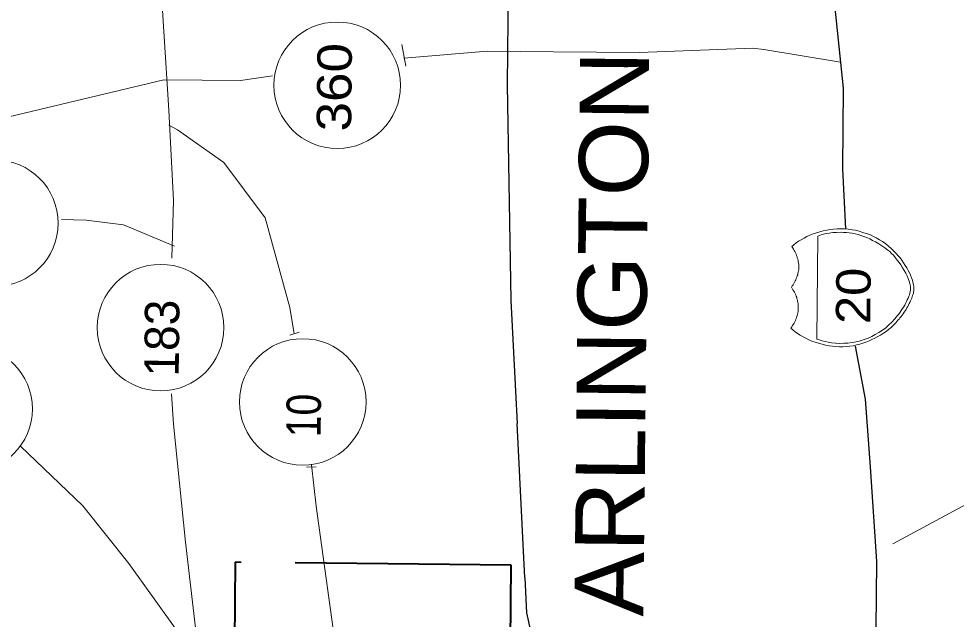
# Model space of a CAD drawing. Extents: x 2356576 to 2377878, y 6966390 to 6990634.
# Drawn here: x 2365828.3 to 2366013.1, y 6969001.5 to 6969120 of the extents above; entities that cross this region are included whole.
import ezdxf

# ---------------------------------------------------------------- set-up
doc = ezdxf.new("R2010")
doc.units = 0
doc.header["$LTSCALE"] = 7.1
doc.linetypes.add('LONG_DASHED', pattern=[7.5, 6, -1.5])
doc.layers.add('19', color=7, linetype='Continuous', lineweight=13)
doc.layers.add('8', color=7, linetype='Continuous', lineweight=13)

msp = doc.modelspace()

# ---------------------------------------------------------------- linework, layer by layer
at = {"layer": '19'}
for p, q in [((2365904.616, 6969110.688), (2365903.821, 6969114.957)), ((2365972.997, 6969114.24), (2365975.214, 6969113.945)), ((2365920.728, 6969113.642), (2365904.18, 6969112.221)), ((2365975.214, 6969113.945), (2365990.313, 6969111.421)), ((2365872.033, 6969107.814), (2365878.283, 6969108.741)), ((2365856.914, 6969107.97), (2365872.033, 6969107.814)), ((2365859.571, 6969098.07), (2365857.841, 6969098.988)), ((2365858.767, 6969084.158), (2365858.437, 6969072.793)), ((2365841.562, 6969080.288), (2365836.703, 6969080.426)), ((2365881.709, 6969063.011), (2365882.528, 6969058.258)), ((2365881.741, 6969057.547), (2365883.547, 6969058.128)), ((2365882.583, 6969057.81), (2365882.528, 6969058.258)), ((2365858.758, 6969040.024), (2365858.372, 6969046)), ((2365840.889, 6969023.86), (2365828.591, 6969035.656)), ((2365884.983, 6969031.504), (2365886.932, 6969031.603)), ((2365886.944, 6969023.831), (2365886.008, 6969032.001))]:
    msp.add_line(p, q, dxfattribs=at)
at = {"layer": '19', "lineweight": 25}
msp.add_line((2365928.079, 6969009.664), (2365926.535, 6969040.134), dxfattribs=at)
at = {"layer": '19'}
for points in [[(2365858.767, 6969084.158), (2365857.839, 6969101.96), (2365855.882, 6969133.094), (2365857.437, 6969161.612), (2365858.594, 6969180.589), (2365859.115, 6969204.617), (2365855.958, 6969218.422), (2365846.578, 6969234.36), (2365837.794, 6969252.124), (2365836.317, 6969257.48)], [(2366155.514, 6969175.953), (2366151.383, 6969165.227), (2366148.79, 6969152.413), (2366143.811, 6969129.392), (2366135.33, 6969115.799), (2366129.355, 6969106.648), (2366121.344, 6969094.85), (2366108.711, 6969083.249), (2366095.035, 6969075.202), (2366079.714, 6969067.44), (2366061.538, 6969056.344), (2366050.004, 6969046.563), (2366038.586, 6969039.093), (2366024.252, 6969030.869), (2366017.685, 6969025.629), (2366000.609, 6969016.381)], [(2365920.728, 6969113.642), (2365933.687, 6969113.507), (2365950.698, 6969113.331), (2365972.997, 6969114.24)], [(2365856.914, 6969107.97), (2365819.074, 6969098.97), (2365792.738, 6969085.174)], [(2365881.709, 6969063.011), (2365876.852, 6969080.702), (2365868.713, 6969091.615), (2365859.571, 6969098.07)], [(2365859.002, 6969075.155), (2365848.936, 6969079.312), (2365841.562, 6969080.288)], [(2365981.222, 6969068.009), (2365981.373, 6969068.279), (2365981.496, 6969068.518), (2365981.59, 6969068.757), (2365981.713, 6969069.024), (2365981.744, 6969069.295), (2365981.866, 6969069.502), (2365981.901, 6969069.774), (2365981.963, 6969070.013), (2365982.026, 6969070.28), (2365982.056, 6969070.52), (2365982.059, 6969070.792), (2365982.062, 6969071.06), (2365982.064, 6969071.3), (2365982.067, 6969071.54), (2365982.042, 6969071.812), (2365981.984, 6969072.053), (2365981.927, 6969072.293), (2365981.898, 6969072.562), (2365981.78, 6969072.803), (2365981.755, 6969073.043), (2365981.637, 6969073.317), (2365981.548, 6969073.585), (2365981.431, 6969073.827), (2365981.285, 6969074.068), (2365981.168, 6969074.309), (2365981.018, 6969074.551), (2365980.841, 6969074.853), (2365980.696, 6969075.094), (2365981.087, 6969075.422), (2365981.543, 6969075.778), (2365982.026, 6969076.101), (2365982.569, 6969076.395), (2365983.112, 6969076.689), (2365983.684, 6969077.016), (2365984.259, 6969077.278), (2365984.889, 6969077.543), (2365985.551, 6969077.744), (2365986.214, 6969077.949), (2365986.908, 6969078.15), (2365987.597, 6969078.295), (2365988.29, 6969078.408), (2365988.951, 6969078.489), (2365989.64, 6969078.542), (2365990.332, 6969078.567), (2365991.08, 6969078.527), (2365991.831, 6969078.459), (2365992.578, 6969078.363), (2365993.269, 6969078.264), (2365993.988, 6969078.109), (2365994.705, 6969077.861), (2365995.391, 6969077.642), (2365996.081, 6969077.427), (2365996.706, 6969077.121), (2365997.362, 6969076.754), (2365997.99, 6969076.415), (2365998.586, 6969076.021), (2365999.21, 6969075.595), (2365999.777, 6969075.137), (2366000.312, 6969074.651), (2366000.875, 6969074.105), (2366001.262, 6969073.681), (2366001.646, 6969073.257), (2366002.033, 6969072.805), (2366002.388, 6969072.35), (2366002.711, 6969071.838), (2366003.066, 6969071.322), (2366003.361, 6969070.839), (2366003.628, 6969070.357), (2366003.891, 6969069.874), (2366004.126, 6969069.391), (2366004.333, 6969068.909), (2366004.476, 6969068.4), (2366004.592, 6969068.006), (2366004.679, 6969067.558), (2366004.763, 6969067.165), (2366004.759, 6969066.805)], [(2366004.759, 6969066.805), (2366004.757, 6969066.565), (2366004.754, 6969066.357), (2366004.692, 6969066.085), (2366004.662, 6969065.878), (2366004.599, 6969065.666), (2366004.505, 6969065.399), (2366004.442, 6969065.128), (2366004.351, 6969064.861), (2366004.228, 6969064.59), (2366004.105, 6969064.323), (2366003.982, 6969064.025), (2366003.86, 6969063.786), (2366003.705, 6969063.487), (2366003.554, 6969063.217), (2366003.399, 6969062.951), (2366003.248, 6969062.652), (2366003.033, 6969062.382), (2366002.85, 6969062.084), (2366002.667, 6969061.786), (2366002.457, 6969061.548), (2366002.274, 6969061.282), (2366002.031, 6969061.013), (2366001.848, 6969060.714), (2366001.634, 6969060.505), (2366001.423, 6969060.239), (2366001.208, 6969060.001), (2366000.966, 6969059.732), (2366000.724, 6969059.526), (2366000.481, 6969059.289), (2366000.271, 6969059.079), (2366000.057, 6969058.901), (2365999.787, 6969058.696), (2365999.303, 6969058.309), (2365998.759, 6969057.954), (2365998.183, 6969057.6), (2365997.672, 6969057.306), (2365997.097, 6969056.983), (2365996.494, 6969056.69), (2365995.923, 6969056.424), (2365995.321, 6969056.19), (2365994.719, 6969055.988), (2365994.084, 6969055.783), (2365993.455, 6969055.641), (2365992.821, 6969055.496), (2365992.16, 6969055.383), (2365991.5, 6969055.329), (2365990.779, 6969055.277), (2365990.091, 6969055.256), (2365989.399, 6969055.323), (2365988.712, 6969055.39), (2365988.053, 6969055.457), (2365987.362, 6969055.612), (2365986.676, 6969055.771), (2365985.986, 6969055.959), (2365985.328, 6969056.173), (2365984.67, 6969056.392), (2365984.045, 6969056.667), (2365983.476, 6969056.945), (2365982.911, 6969057.25), (2365982.374, 6969057.584), (2365981.838, 6969057.922), (2365981.361, 6969058.227), (2365980.913, 6969058.591), (2365980.528, 6969058.923), (2365980.679, 6969059.194), (2365980.862, 6969059.46), (2365981.017, 6969059.73), (2365981.139, 6969059.937), (2365981.29, 6969060.207), (2365981.412, 6969060.446), (2365981.507, 6969060.713), (2365981.63, 6969060.984), (2365981.66, 6969061.224), (2365981.783, 6969061.462), (2365981.817, 6969061.734), (2365981.88, 6969061.973), (2365981.943, 6969062.241), (2365981.973, 6969062.48), (2365981.976, 6969062.72), (2365981.979, 6969063.02), (2365981.981, 6969063.232), (2365981.984, 6969063.5), (2365981.958, 6969063.741), (2365981.901, 6969064.013), (2365981.843, 6969064.254), (2365981.814, 6969064.494), (2365981.697, 6969064.763), (2365981.672, 6969065.036), (2365981.554, 6969065.245), (2365981.465, 6969065.518), (2365981.347, 6969065.787), (2365981.202, 6969066.061), (2365981.084, 6969066.27), (2365980.935, 6969066.543), (2365980.758, 6969066.785), (2365980.612, 6969067.055), (2365980.763, 6969067.293), (2365980.945, 6969067.503), (2365981.1, 6969067.77), (2365981.222, 6969068.009)], [(2365864.052, 6968991.934), (2365861.157, 6969016.718), (2365858.758, 6969040.024)], [(2365840.889, 6969023.86), (2365850.012, 6969012.481), (2365864.416, 6968992.29)], [(2365886.944, 6969023.831), (2365890.88, 6968995.288), (2365892.792, 6968930.793), (2365894.338, 6968920.933)]]:
    msp.add_lwpolyline(points, dxfattribs=at)
at = {"layer": '19', "lineweight": 25}
for points in [[(2365915.489, 6969256.66), (2365917.015, 6969239.123), (2365920.491, 6969212.413), (2365923.907, 6969180.304), (2365924.96, 6969145.7), (2365924.559, 6969106.97), (2365925.286, 6969064.388), (2365926.535, 6969040.134)], [(2366011.996, 6969255.66), (2366002.067, 6969238.242), (2365996.913, 6969215.73), (2365990.557, 6969192.935), (2365988.816, 6969161.211), (2365987.454, 6969142.5), (2365988.484, 6969129.141), (2365990.827, 6969106.283), (2365990.663, 6969090.412), (2365991.32, 6969078.497)], [(2365993.212, 6969055.404), (2365995.144, 6969044.943), (2365996.174, 6969031.612), (2365997.392, 6969012.874), (2365997.254, 6968999.555), (2365998.323, 6968990.003), (2366002.006, 6968983.305), (2366004.476, 6968969.926), (2366002.874, 6968951.222), (2366001.496, 6968934.107), (2366000.162, 6968915.368), (2366003.604, 6968885.811), (2365999.567, 6968857.919), (2365994.142, 6968835.442), (2365986.716, 6968822.166), (2365969.062, 6968818.241), (2365951.423, 6968818.424), (2365942.698, 6968815.994), (2365930.315, 6968822.751)], [(2365928.079, 6969009.664), (2365928.4, 6969002.788), (2365929.974, 6968995.604)]]:
    msp.add_lwpolyline(points, dxfattribs=at)
at = {"layer": '19'}
msp.add_lwpolyline([(2365985.845, 6969077.113), (2365985.634, 6969056.802), (2365985.934, 6969056.707), (2365986.292, 6969056.555), (2365986.711, 6969056.431), (2365987.282, 6969056.333), (2365987.848, 6969056.179), (2365988.539, 6969056.052), (2365989.286, 6969055.984), (2365990.098, 6969055.944), (2365990.938, 6969055.967), (2365991.779, 6969056.019), (2365992.62, 6969056.13), (2365993.401, 6969056.27), (2365994.212, 6969056.473), (2365994.966, 6969056.706), (2365995.749, 6969056.997), (2365996.472, 6969057.318), (2365997.164, 6969057.671), (2365997.888, 6969058.083), (2365998.553, 6969058.528), (2365999.218, 6969059.03), (2365999.856, 6969059.595), (2366000.43, 6969060.157), (2366001.009, 6969060.783), (2366001.523, 6969061.438), (2366001.826, 6969061.735), (2366002.042, 6969062.093), (2366002.286, 6969062.422), (2366002.498, 6969062.808), (2366002.713, 6969063.106), (2366002.956, 6969063.463), (2366003.14, 6969063.821), (2366003.324, 6969064.211), (2366003.476, 6969064.538), (2366003.631, 6969064.896), (2366003.783, 6969065.255), (2366003.878, 6969065.554), (2366003.97, 6969065.885), (2366004.033, 6969066.184), (2366004.096, 6969066.512), (2366004.099, 6969066.811), (2366004.076, 6969067.232), (2366003.989, 6969067.745), (2366003.813, 6969068.195), (2366003.639, 6969068.768), (2366003.465, 6969069.278), (2366003.17, 6969069.793), (2366002.876, 6969070.336), (2366002.553, 6969070.88), (2366002.199, 6969071.423), (2366001.844, 6969071.907), (2366001.489, 6969072.391), (2366001.102, 6969072.875), (2366000.746, 6969073.327), (2366000.362, 6969073.691), (2366000.006, 6969074.054), (2365999.649, 6969074.33), (2365999.053, 6969074.784), (2365998.426, 6969075.211), (2365997.862, 6969075.609), (2365997.206, 6969075.975), (2365996.637, 6969076.281), (2365996.072, 6969076.555), (2365995.503, 6969076.833), (2365994.905, 6969077.047), (2365994.307, 6969077.265), (2365993.769, 6969077.451), (2365993.17, 6969077.577), (2365992.603, 6969077.671), (2365992.032, 6969077.737), (2365991.465, 6969077.835), (2365990.893, 6969077.841), (2365990.325, 6969077.875), (2365989.513, 6969077.855), (2365988.764, 6969077.803), (2365988.071, 6969077.718), (2365987.502, 6969077.636), (2365986.929, 6969077.49), (2365986.507, 6969077.346), (2365986.146, 6969077.23)], close=True, dxfattribs=at)
at = {"layer": '19', "linetype": 'LONG_DASHED', "lineweight": 40}
msp.add_lwpolyline([(2365875.35, 6968982.009), (2365925.059, 6968981.494), (2365925.377, 6969012.18), (2365870.956, 6969012.744), (2365870.638, 6968982.057)], close=True, dxfattribs=at)
at = {"layer": '19'}
for centre in [(2365891.07, 6969106.881), (2365823.565, 6969079.667), (2365856.243, 6969059.06), (2365884.28, 6969044.389), (2365818.484, 6969043.016)]:
    msp.add_circle(centre, 12.486, dxfattribs=at)
at = {"layer": '8'}
for p, q in [((2365904.616, 6969110.688), (2365903.821, 6969114.957)), ((2365972.997, 6969114.24), (2365975.214, 6969113.945)), ((2365920.728, 6969113.642), (2365904.18, 6969112.221)), ((2365975.214, 6969113.945), (2365990.313, 6969111.421)), ((2365872.033, 6969107.814), (2365878.283, 6969108.741)), ((2365856.914, 6969107.97), (2365872.033, 6969107.814)), ((2365859.571, 6969098.07), (2365857.841, 6969098.988)), ((2365858.767, 6969084.158), (2365858.437, 6969072.793)), ((2365841.562, 6969080.288), (2365836.703, 6969080.426)), ((2365881.709, 6969063.011), (2365882.528, 6969058.258)), ((2365881.741, 6969057.547), (2365883.547, 6969058.128)), ((2365882.583, 6969057.81), (2365882.528, 6969058.258)), ((2365858.758, 6969040.024), (2365858.372, 6969046)), ((2365840.889, 6969023.86), (2365828.591, 6969035.656)), ((2365884.983, 6969031.504), (2365886.932, 6969031.603)), ((2365886.944, 6969023.831), (2365886.008, 6969032.001))]:
    msp.add_line(p, q, dxfattribs=at)
at = {"layer": '8', "lineweight": 25}
msp.add_line((2365928.079, 6969009.664), (2365926.535, 6969040.134), dxfattribs=at)
at = {"layer": '8'}
for points in [[(2365858.767, 6969084.158), (2365857.839, 6969101.96), (2365855.882, 6969133.094), (2365857.437, 6969161.612), (2365858.594, 6969180.589), (2365859.115, 6969204.617), (2365855.958, 6969218.422), (2365846.578, 6969234.36), (2365837.794, 6969252.124), (2365836.317, 6969257.48)], [(2366155.514, 6969175.953), (2366151.383, 6969165.227), (2366148.79, 6969152.413), (2366143.811, 6969129.392), (2366135.33, 6969115.799), (2366129.355, 6969106.648), (2366121.344, 6969094.85), (2366108.711, 6969083.249), (2366095.035, 6969075.202), (2366079.714, 6969067.44), (2366061.538, 6969056.344), (2366050.004, 6969046.563), (2366038.586, 6969039.093), (2366024.252, 6969030.869), (2366017.685, 6969025.629), (2366000.609, 6969016.381)], [(2365920.728, 6969113.642), (2365933.687, 6969113.507), (2365950.698, 6969113.331), (2365972.997, 6969114.24)], [(2365856.914, 6969107.97), (2365819.074, 6969098.97), (2365792.738, 6969085.174)], [(2365881.709, 6969063.011), (2365876.852, 6969080.702), (2365868.713, 6969091.615), (2365859.571, 6969098.07)], [(2365859.002, 6969075.155), (2365848.936, 6969079.312), (2365841.562, 6969080.288)], [(2365981.222, 6969068.009), (2365981.373, 6969068.279), (2365981.496, 6969068.518), (2365981.59, 6969068.757), (2365981.713, 6969069.024), (2365981.744, 6969069.295), (2365981.866, 6969069.502), (2365981.901, 6969069.774), (2365981.963, 6969070.013), (2365982.026, 6969070.28), (2365982.056, 6969070.52), (2365982.059, 6969070.792), (2365982.062, 6969071.06), (2365982.064, 6969071.3), (2365982.067, 6969071.54), (2365982.042, 6969071.812), (2365981.984, 6969072.053), (2365981.927, 6969072.293), (2365981.898, 6969072.562), (2365981.78, 6969072.803), (2365981.755, 6969073.043), (2365981.637, 6969073.317), (2365981.548, 6969073.585), (2365981.431, 6969073.827), (2365981.285, 6969074.068), (2365981.168, 6969074.309), (2365981.018, 6969074.551), (2365980.841, 6969074.853), (2365980.696, 6969075.094), (2365981.087, 6969075.422), (2365981.543, 6969075.778), (2365982.026, 6969076.101), (2365982.569, 6969076.395), (2365983.112, 6969076.689), (2365983.684, 6969077.016), (2365984.259, 6969077.278), (2365984.889, 6969077.543), (2365985.551, 6969077.744), (2365986.214, 6969077.949), (2365986.908, 6969078.15), (2365987.597, 6969078.295), (2365988.29, 6969078.408), (2365988.951, 6969078.489), (2365989.64, 6969078.542), (2365990.332, 6969078.567), (2365991.08, 6969078.527), (2365991.831, 6969078.459), (2365992.578, 6969078.363), (2365993.269, 6969078.264), (2365993.988, 6969078.109), (2365994.705, 6969077.861), (2365995.391, 6969077.642), (2365996.081, 6969077.427), (2365996.706, 6969077.121), (2365997.362, 6969076.754), (2365997.99, 6969076.415), (2365998.586, 6969076.021), (2365999.21, 6969075.595), (2365999.777, 6969075.137), (2366000.312, 6969074.651), (2366000.875, 6969074.105), (2366001.262, 6969073.681), (2366001.646, 6969073.257), (2366002.033, 6969072.805), (2366002.388, 6969072.35), (2366002.711, 6969071.838), (2366003.066, 6969071.322), (2366003.361, 6969070.839), (2366003.628, 6969070.357), (2366003.891, 6969069.874), (2366004.126, 6969069.391), (2366004.333, 6969068.909), (2366004.476, 6969068.4), (2366004.592, 6969068.006), (2366004.679, 6969067.558), (2366004.763, 6969067.165), (2366004.759, 6969066.805)], [(2366004.759, 6969066.805), (2366004.757, 6969066.565), (2366004.754, 6969066.357), (2366004.692, 6969066.085), (2366004.662, 6969065.878), (2366004.599, 6969065.666), (2366004.505, 6969065.399), (2366004.442, 6969065.128), (2366004.351, 6969064.861), (2366004.228, 6969064.59), (2366004.105, 6969064.323), (2366003.982, 6969064.025), (2366003.86, 6969063.786), (2366003.705, 6969063.487), (2366003.554, 6969063.217), (2366003.399, 6969062.951), (2366003.248, 6969062.652), (2366003.033, 6969062.382), (2366002.85, 6969062.084), (2366002.667, 6969061.786), (2366002.457, 6969061.548), (2366002.274, 6969061.282), (2366002.031, 6969061.013), (2366001.848, 6969060.714), (2366001.634, 6969060.505), (2366001.423, 6969060.239), (2366001.208, 6969060.001), (2366000.966, 6969059.732), (2366000.724, 6969059.526), (2366000.481, 6969059.289), (2366000.271, 6969059.079), (2366000.057, 6969058.901), (2365999.787, 6969058.696), (2365999.303, 6969058.309), (2365998.759, 6969057.954), (2365998.183, 6969057.6), (2365997.672, 6969057.306), (2365997.097, 6969056.983), (2365996.494, 6969056.69), (2365995.923, 6969056.424), (2365995.321, 6969056.19), (2365994.719, 6969055.988), (2365994.084, 6969055.783), (2365993.455, 6969055.641), (2365992.821, 6969055.496), (2365992.16, 6969055.383), (2365991.5, 6969055.329), (2365990.779, 6969055.277), (2365990.091, 6969055.256), (2365989.399, 6969055.323), (2365988.712, 6969055.39), (2365988.053, 6969055.457), (2365987.362, 6969055.612), (2365986.676, 6969055.771), (2365985.986, 6969055.959), (2365985.328, 6969056.173), (2365984.67, 6969056.392), (2365984.045, 6969056.667), (2365983.476, 6969056.945), (2365982.911, 6969057.25), (2365982.374, 6969057.584), (2365981.838, 6969057.922), (2365981.361, 6969058.227), (2365980.913, 6969058.591), (2365980.528, 6969058.923), (2365980.679, 6969059.194), (2365980.862, 6969059.46), (2365981.017, 6969059.73), (2365981.139, 6969059.937), (2365981.29, 6969060.207), (2365981.412, 6969060.446), (2365981.507, 6969060.713), (2365981.63, 6969060.984), (2365981.66, 6969061.224), (2365981.783, 6969061.462), (2365981.817, 6969061.734), (2365981.88, 6969061.973), (2365981.943, 6969062.241), (2365981.973, 6969062.48), (2365981.976, 6969062.72), (2365981.979, 6969063.02), (2365981.981, 6969063.232), (2365981.984, 6969063.5), (2365981.958, 6969063.741), (2365981.901, 6969064.013), (2365981.843, 6969064.254), (2365981.814, 6969064.494), (2365981.697, 6969064.763), (2365981.672, 6969065.036), (2365981.554, 6969065.245), (2365981.465, 6969065.518), (2365981.347, 6969065.787), (2365981.202, 6969066.061), (2365981.084, 6969066.27), (2365980.935, 6969066.543), (2365980.758, 6969066.785), (2365980.612, 6969067.055), (2365980.763, 6969067.293), (2365980.945, 6969067.503), (2365981.1, 6969067.77), (2365981.222, 6969068.009)], [(2365864.052, 6968991.934), (2365861.157, 6969016.718), (2365858.758, 6969040.024)], [(2365840.889, 6969023.86), (2365850.012, 6969012.481), (2365864.416, 6968992.29)], [(2365886.944, 6969023.831), (2365890.88, 6968995.288), (2365892.792, 6968930.793), (2365894.338, 6968920.933)]]:
    msp.add_lwpolyline(points, dxfattribs=at)
at = {"layer": '8', "lineweight": 25}
for points in [[(2365915.489, 6969256.66), (2365917.015, 6969239.123), (2365920.491, 6969212.413), (2365923.907, 6969180.304), (2365924.96, 6969145.7), (2365924.559, 6969106.97), (2365925.286, 6969064.388), (2365926.535, 6969040.134)], [(2366011.996, 6969255.66), (2366002.067, 6969238.242), (2365996.913, 6969215.73), (2365990.557, 6969192.935), (2365988.816, 6969161.211), (2365987.454, 6969142.5), (2365988.484, 6969129.141), (2365990.827, 6969106.283), (2365990.663, 6969090.412), (2365991.32, 6969078.497)], [(2365993.212, 6969055.404), (2365995.144, 6969044.943), (2365996.174, 6969031.612), (2365997.392, 6969012.874), (2365997.254, 6968999.555), (2365998.323, 6968990.003), (2366002.006, 6968983.305), (2366004.476, 6968969.926), (2366002.874, 6968951.222), (2366001.496, 6968934.107), (2366000.162, 6968915.368), (2366003.604, 6968885.811), (2365999.567, 6968857.919), (2365994.142, 6968835.442), (2365986.716, 6968822.166), (2365969.062, 6968818.241), (2365951.423, 6968818.424), (2365942.698, 6968815.994), (2365930.315, 6968822.751)], [(2365928.079, 6969009.664), (2365928.4, 6969002.788), (2365929.974, 6968995.604)]]:
    msp.add_lwpolyline(points, dxfattribs=at)
at = {"layer": '8'}
msp.add_lwpolyline([(2365985.845, 6969077.113), (2365985.634, 6969056.802), (2365985.934, 6969056.707), (2365986.292, 6969056.555), (2365986.711, 6969056.431), (2365987.282, 6969056.333), (2365987.848, 6969056.179), (2365988.539, 6969056.052), (2365989.286, 6969055.984), (2365990.098, 6969055.944), (2365990.938, 6969055.967), (2365991.779, 6969056.019), (2365992.62, 6969056.13), (2365993.401, 6969056.27), (2365994.212, 6969056.473), (2365994.966, 6969056.706), (2365995.749, 6969056.997), (2365996.472, 6969057.318), (2365997.164, 6969057.671), (2365997.888, 6969058.083), (2365998.553, 6969058.528), (2365999.218, 6969059.03), (2365999.856, 6969059.595), (2366000.43, 6969060.157), (2366001.009, 6969060.783), (2366001.523, 6969061.438), (2366001.826, 6969061.735), (2366002.042, 6969062.093), (2366002.286, 6969062.422), (2366002.498, 6969062.808), (2366002.713, 6969063.106), (2366002.956, 6969063.463), (2366003.14, 6969063.821), (2366003.324, 6969064.211), (2366003.476, 6969064.538), (2366003.631, 6969064.896), (2366003.783, 6969065.255), (2366003.878, 6969065.554), (2366003.97, 6969065.885), (2366004.033, 6969066.184), (2366004.096, 6969066.512), (2366004.099, 6969066.811), (2366004.076, 6969067.232), (2366003.989, 6969067.745), (2366003.813, 6969068.195), (2366003.639, 6969068.768), (2366003.465, 6969069.278), (2366003.17, 6969069.793), (2366002.876, 6969070.336), (2366002.553, 6969070.88), (2366002.199, 6969071.423), (2366001.844, 6969071.907), (2366001.489, 6969072.391), (2366001.102, 6969072.875), (2366000.746, 6969073.327), (2366000.362, 6969073.691), (2366000.006, 6969074.054), (2365999.649, 6969074.33), (2365999.053, 6969074.784), (2365998.426, 6969075.211), (2365997.862, 6969075.609), (2365997.206, 6969075.975), (2365996.637, 6969076.281), (2365996.072, 6969076.555), (2365995.503, 6969076.833), (2365994.905, 6969077.047), (2365994.307, 6969077.265), (2365993.769, 6969077.451), (2365993.17, 6969077.577), (2365992.603, 6969077.671), (2365992.032, 6969077.737), (2365991.465, 6969077.835), (2365990.893, 6969077.841), (2365990.325, 6969077.875), (2365989.513, 6969077.855), (2365988.764, 6969077.803), (2365988.071, 6969077.718), (2365987.502, 6969077.636), (2365986.929, 6969077.49), (2365986.507, 6969077.346), (2365986.146, 6969077.23)], close=True, dxfattribs=at)
at = {"layer": '8', "linetype": 'LONG_DASHED', "lineweight": 40}
msp.add_lwpolyline([(2365875.35, 6968982.009), (2365925.059, 6968981.494), (2365925.377, 6969012.18), (2365870.956, 6969012.744), (2365870.638, 6968982.057)], close=True, dxfattribs=at)
at = {"layer": '8'}
for centre in [(2365891.07, 6969106.881), (2365823.565, 6969079.667), (2365856.243, 6969059.06), (2365884.28, 6969044.389), (2365818.484, 6969043.016)]:
    msp.add_circle(centre, 12.486, dxfattribs=at)

# ---------------------------------------------------------------- texts
at = {"layer": '19'}
for s, height, width, p in [('360', 6.798, 1.15, (2365893.802, 6969097.748)), ('ARLINGTON', 13.62, 1.05, (2365951.433, 6969002.01)), ('20', 6.798, 1.1, (2365996.165, 6969059.721)), ('10', 6.798, 0.85, (2365887.804, 6969037.383))]:
    msp.add_text(s, height=height, rotation=89.406, dxfattribs=dict(at, width=width)).set_placement(p)
msp.add_text('183', height=6.798, rotation=89.406, dxfattribs=at).set_placement((2365859.815, 6969049.373))
at = {"layer": '8'}
for s, height, width, p in [('360', 6.798, 1.15, (2365893.802, 6969097.748)), ('ARLINGTON', 13.62, 1.05, (2365951.433, 6969002.01)), ('20', 6.798, 1.1, (2365996.165, 6969059.721)), ('10', 6.798, 0.85, (2365887.804, 6969037.383))]:
    msp.add_text(s, height=height, rotation=89.406, dxfattribs=dict(at, width=width)).set_placement(p)
msp.add_text('183', height=6.798, rotation=89.406, dxfattribs=at).set_placement((2365859.815, 6969049.373))

doc.saveas('drawing.dxf')
